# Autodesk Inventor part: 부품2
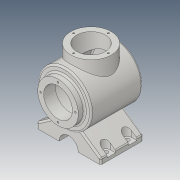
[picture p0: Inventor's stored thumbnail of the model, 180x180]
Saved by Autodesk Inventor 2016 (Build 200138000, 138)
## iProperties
Created: 2017-04
Part Number: 부품2
Material: 알루미늄 6061
Document SubType Name: Modeling
Designer: Administrator
Density: 2.7 g/cm^3
Appearance: 눈
Mass: 1657.09 g
Surface Area: 1071.91 cm^2
Volume: 613.738 cm^3
Author: Administrator
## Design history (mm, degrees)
sketch "스케치1"
  geometry: L1 (-60, 2.834)-(-60, 12.834); L2 (-60, 12.834)-(-17.156, 42.834); L3 (-17.156, 42.834)-(17.156, 42.834); L4 (17.156, 42.834)-(60, 12.834); L5 (60, 12.834)-(60, 2.834); L6 (60, 2.834)-(-60, 2.834); 1 further point
  constraints: 12 end point, 2 perpendicular, 1 parallel, 1 vertical
  dimensions: "d0" = 120 distance of L5.end L1.start; "d1" = 10 distance of L4.end L5.end; "d2" = 10 distance of L1.start L1.end; "d3" = 55 deg angle of L2 L1; "d4" = 55 deg angle of L5 L4; "d5" = 40 distance between parallel lines of L6 L3; "d25" = 60 distance from line of point (0, 0) L1
extrude "돌출1" new body sketch "스케치1" stored distance "d6" = 80; taper "d7" = 0 deg
sketch "스케치2"
  geometry: L1 (42.834, -40)-(2.834, -40) reference; L2 (2.834, -40)-(2.834, 40) reference; L3 (2.834, 40)-(42.834, 40) reference; L4 (42.834, 40)-(42.834, -40) reference; L5 (84.834, -60)-(84.834, 48); L6 (84.834, 48)-(134.834, 48); L7 (134.834, 48)-(134.834, -47.617); L8 (134.834, -60)-(84.834, -60); L9 (116.006, 53)-(59.177, 53); L10 (84.834, 48)-(84.834, 65.284); A1 r 113 centre (83.384, 52.991) between (84.834, -60) and (134.834, -47.617); 1 further point
  constraints: 12 end point, 3 perpendicular, 2 point on circle, 2 vertical, 1 centre point, 1 horizontal, 1 point on line
  dimensions: "d9" = 82 distance between parallel lines of L2 L5; "d10" = 100 diameter of L7 L5; "d11" = 8 distance between parallel lines of L3 L6; "d12" = 113 distance between parallel lines of L8 L9; "d16" = 113 radius of A1; "d108" = 108 distance from line of A1.start L6
revolve "회전1" sketch "스케치2" stored, may be unused: angle "d17" = 90 deg
sketch "스케치3"
  geometry: C1 r 50 at (0, 0) reference; C2 r 38 at (0, 0); 1 further point
  constraints: 1 centre point, 1 coincident
  dimensions: "d18" = 76 diameter of C2
extrude "돌출2" join sketch "스케치3" distance "d19" = 12; taper "d20" = 0 deg
node "작업 평면1"
sketch "스케치4"
  geometry: L1 (10, 8)-(110, 8) reference; C1 r 38 at (60, -42); 1 further point
  constraints: 1 centre point
  dimensions: "d91" = 76 diameter of C1; "d92" = 50 distance from line of L1 C1.centre
extrude "돌출3" join sketch "스케치4" stored distance "d23" = 12; taper "d24" = 0 deg
sketch "스케치5"
  geometry: L1 (-21.584, 39.732)-(-60, 12.834) reference; L2 (-60, 12.834)-(-60, 2.834) reference; L3 (-60, 2.834)-(60, 2.834) reference; L4 (60, 2.834)-(60, 12.834) reference; L5 (60, 12.834)-(21.584, 39.732) reference; A1 r 50 centre (0, 84.834) between (-21.584, 39.732) and (21.584, 39.732) reference; 1 further point
sketch "스케치6"
  geometry: L1 (-60, 2.834)-(60, 2.834) reference; C1 r 18 at (0, 2.834); 1 further point
  constraints: 1 centre point, 1 midpoint
  dimensions: "d26" = 36 diameter of C1
extrude "돌출4" cut sketch "스케치6" stored distance "d27" = 12; taper "d28" = 0 deg
node "작업 평면2"
sketch "스케치7"
  geometry: L1 (-87.129, -7.617)-(-87.129, 88) reference; L2 (-87.129, 88)-(-32.871, 88) reference; L3 (-32.871, 88)-(-32.871, -7.617) reference; L4 (-38.416, 0)-(-38.416, 80) reference; L5 (0, 80)-(-38.416, 80) reference; L6 (0, 80)-(0, 0) reference; L7 (-38.416, 0)-(0, 0) reference; L8 (-10, 52)-(0, 52); L9 (-10, 68)-(0, 68); L10 (-10, 28)-(0, 28); L11 (-10, 12)-(0, 12); A1 r 8 centre (-10, 60) between (-10, 68) and (-10, 52); A2 r 8 centre (-10, 20) between (-10, 28) and (-10, 12); 1 further point
  constraints: 8 end point, 4 point on circle, 4 point on line, 3 horizontal, 2 centre point, 1 horizontal alignment, 1 perpendicular, 1 tangent
  dimensions: "d30" = 16 diameter of A1; "d31" = 16 diameter of A2; "d32" = 20 vertical distance of point (-60, 40) A1.centre; "d33" = 20 vertical distance of A2.centre point (-60, 40); "d34" = 10 distance from line of L6 A2.centre; "d35" = 10 distance from line of L6 A1.centre
extrude "돌출5" cut sketch "스케치7" distance "d36" = 34; taper "d37" = 0 deg
sketch "스케치8"
  geometry: A1 r 8 centre (-10, -60) between (-10, -52) and (-10, -68) reference; 1 further point
hole "구멍1" sketch "스케치8" at (-10, -60) diameter "d38" = 8; stored, may be unused: countersink angle "d42" = 90 deg, drill point angle "d44" = 118 deg; dims "d39" = 6, "d40" = 4, "d41" = 2, "d43" = 8
sketch "스케치9"
  geometry: A1 r 8 centre (-10, -20) between (-10, -12) and (-10, -28) reference; 1 further point
hole "구멍2" sketch "스케치9" at (-10, -20) diameter "d45" = 8; stored, may be unused: countersink angle "d49" = 90 deg, drill point angle "d51" = 118 deg; dims "d46" = 6, "d47" = 4, "d48" = 2, "d50" = 8
node "작업 평면3"
sketch "스케치10"
  geometry: L1 (-20, 120)-(-8, 120) reference; L2 (-8, 120)-(-8, 132) reference; L3 (-8, 132)-(4, 132) reference; L4 (80, 132)-(87.617, 132) reference; L5 (87.617, 32)-(80, 32) reference; L6 (80, 32)-(80, 18) reference; L7 (80, 18)-(0, 18) reference; L8 (0, 18)-(0, 32) reference; L9 (0, 32)-(-8, 32) reference; L10 (-8, 32)-(-8, 44) reference; L11 (-8, 44)-(-20, 44) reference; L12 (-20, 44)-(-20, 120) reference; L13 (-20, 120)-(-20, 44) reference; L14 (-20, 82)-(89.999, 82); L15 (79.322, 122)-(5, 122); L16 (2, 119)-(2, 109); L17 (2, 109)-(-20, 109); L18 (4, 132)-(4, 147) reference; L19 (4, 147)-(80, 147) reference; L20 (80, 147)-(80, 132) reference; A1 r 113 centre (-12.991, 80.55) between (100, 82) and (87.617, 132) reference; A2 r 113 centre (-12.991, 83.45) between (87.617, 32) and (100, 82) reference; A3 r 103 centre (-12.991, 80.55) between (89.999, 82) and (82.091, 120.153); A4 r 102.942 centre (-12.991, 83.45) between (81.532, 42.676) and (82.092, 44); A5 r 3 centre (5, 119) between (5, 122) and (2, 119); A6 r 3 centre (79.322, 119) between (82.091, 120.153) and (79.322, 122); 2 further points
  constraints: 9 point on circle, 8 end point, 4 centre point, 4 tangent, 3 point on line, 2 perpendicular, 1 equal radius, 1 horizontal, 1 midpoint
  dimensions: "d52" = 22 distance of L16.end L17.end; "d55" = 10 radial gap between concentric circles of A1 A3; "d56" = 54 diameter of L17 L14; "d57" = 80 diameter of L15 L14; "d58" = 3 radius of A5
  node "절단 모서리 투영3"
sketch "스케치12"
  geometry: C1 r 27 at (0, 0) reference; 2 further points
  dimensions: "d63" = 32.5 distance of C1.centre point (0, 32.5)
hole "구멍3" sketch "스케치12" at (0, 32.5) diameter "d64" = 3.242; stored, may be unused: countersink angle "d68" = 90 deg, drill point angle "d70" = 118 deg; dims "d65" = 8, "d66" = 4, "d67" = 2, "d69" = 10
node "작업축1"
node "작업축2"
fillet "모깎기1" dims "d84" = 3
fillet "모깎기2" dims "d85" = 3
fillet "모깎기3" dims "d86" = 3
node "작업 평면4"
revolve "회전3" stored, may be unused: angle "d93" = 90 deg
sketch "스케치15"
  geometry: C1 r 38 at (0, 0) reference; C2 r 27 at (0, 0); 1 further point
  constraints: 1 centre point, 1 coincident
  dimensions: "d94" = 54 diameter of C2
extrude "돌출7" cut sketch "스케치15" stored distance "d95" = 10; taper "d96" = 0 deg
sketch "스케치16"
  geometry: C1 r 27 at (0, 0) reference; 2 further points
  dimensions: "d97" = 32.5 distance of point (0, 32.5) C1.centre
hole "구멍5" sketch "스케치16" at (0, 32.5) diameter "d98" = 3.242; stored, may be unused: countersink angle "d102" = 90 deg, drill point angle "d104" = 118 deg; dims "d99" = 8, "d100" = 4, "d101" = 2, "d103" = 10
node "작업축3"
node "작업 평면5"
sketch "스케치17"
  geometry: 1 further point
node "솔리드1"
mirror "대칭1"
pattern_circular "원형 패턴1" dims angle "d72" = 360 deg
pattern_circular "원형 패턴3" dims angle "d106" = 360 deg
node "투영된 루프1"
node "절단 모서리 투영1"
node "절단 모서리 투영2"
other parameters: "d15" = 226, "d21" = -147, "d109" = -108
